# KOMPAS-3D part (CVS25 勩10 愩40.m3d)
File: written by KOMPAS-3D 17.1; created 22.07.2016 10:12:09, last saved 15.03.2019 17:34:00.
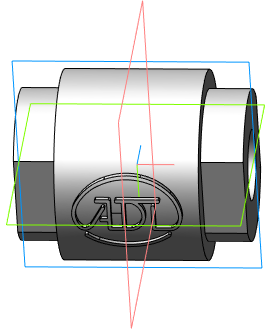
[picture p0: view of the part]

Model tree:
1. Операция без истории:2  (labels: Сталь 20  ГОСТ 1050-88)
